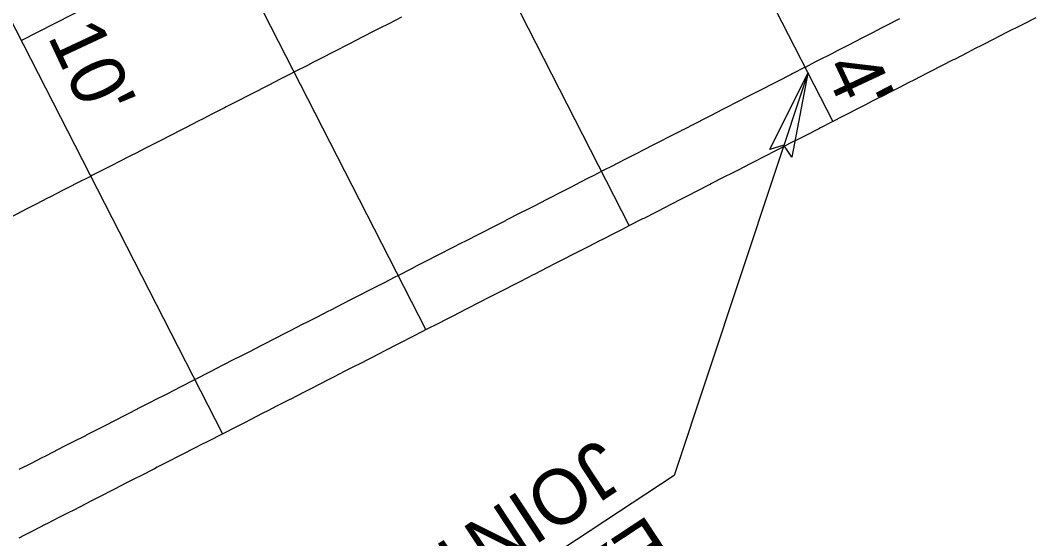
# Model space of a CAD drawing. Extents: x 2145147 to 2158018, y 137519 to 148068.
# Drawn here: x 2149836.3 to 2149903, y 143253.3 to 143287.3 of the extents above; entities that cross this region are included whole.
import ezdxf

# ---------------------------------------------------------------- set-up
doc = ezdxf.new("R2010")
doc.units = 0
for name, color, linetype in [('PR_Align_Service_C_Leader', 7, 'Continuous'), ('PR_Align_Service_C_Txt', 7, 'Continuous'), ('PR_Arrows', 7, 'Continuous'), ('PR_Dimensions', 7, 'Continuous'), ('PR_Joint_Contraction', 7, 'Continuous'), ('PR_Joint_Isolation', 7, 'Continuous'), ('PR_Joint_Long', 7, 'Continuous'), ('PR_Road_Concrete', 7, 'Continuous')]:
    doc.layers.add(name, color=color, linetype=linetype)

msp = doc.modelspace()

# ---------------------------------------------------------------- linework, layer by layer
at = {"layer": 'PR_Align_Service_C_Leader'}
msp.add_lwpolyline([(2149887.995, 143283.862), (2149879.208, 143257.447), (2149850.812, 143238.737)], dxfattribs=at)
at = {"layer": 'PR_Arrows'}
msp.add_lwpolyline([(2149887.995, 143283.862), (2149886.949, 143278.347), (2149886.421, 143279.131), (2149885.498, 143278.839)], close=True, dxfattribs=at)
at = {"layer": 'PR_Joint_Contraction'}
for p, q in [((2149859.056, 143307.493), (2149876.27, 143273.847)), ((2149847.09, 143297.948), (2149862.916, 143267.015)), ((2149835.031, 143288.585), (2149849.562, 143260.183))]:
    msp.add_line(p, q, dxfattribs=at)
at = {"layer": 'PR_Joint_Isolation'}
msp.add_line((2149876.415, 143306.496), (2149889.624, 143280.679), dxfattribs=at)
at = {"layer": 'PR_Joint_Long'}
msp.add_line((2149876.415, 143306.497), (2149836.353, 143286.001), dxfattribs=at)
for points in [[(2149861.301, 143287.53), (2149860.471, 143287.106), (2149859.85, 143286.788), (2149859.581, 143286.65), (2149858.691, 143286.195), (2149858.398, 143286.045), (2149857.801, 143285.739), (2149856.946, 143285.302), (2149856.91, 143285.284), (2149856.02, 143284.828), (2149855.495, 143284.559), (2149855.13, 143284.373), (2149854.24, 143283.917), (2149854.043, 143283.817), (2149853.349, 143283.462), (2149852.591, 143283.074), (2149852.459, 143283.006), (2149851.569, 143282.551), (2149851.139, 143282.331), (2149850.679, 143282.095), (2149849.788, 143281.64), (2149849.688, 143281.588), (2149848.898, 143281.185), (2149848.236, 143280.846), (2149848.008, 143280.729), (2149847.118, 143280.274), (2149846.784, 143280.103), (2149846.227, 143279.818), (2149845.337, 143279.363), (2149845.332, 143279.36), (2149844.447, 143278.907), (2149843.881, 143278.618), (2149843.557, 143278.452), (2149842.666, 143277.996), (2149842.429, 143277.875), (2149841.776, 143277.541), (2149840.977, 143277.132), (2149840.886, 143277.085), (2149839.996, 143276.63), (2149839.525, 143276.389), (2149839.105, 143276.174), (2149838.215, 143275.719), (2149838.074, 143275.647), (2149837.325, 143275.263), (2149836.622, 143274.904), (2149836.435, 143274.808), (2149835.544, 143274.353)], [(2149894.011, 143287.416), (2149893.121, 143286.96), (2149892.813, 143286.803), (2149892.23, 143286.505), (2149891.361, 143286.06), (2149891.34, 143286.049), (2149890.45, 143285.594), (2149889.909, 143285.317), (2149889.56, 143285.138), (2149888.669, 143284.683), (2149888.458, 143284.575), (2149887.807, 143284.242), (2149887.802, 143284.239), (2149887.779, 143284.228), (2149887.006, 143283.832), (2149886.889, 143283.772), (2149885.999, 143283.317), (2149885.554, 143283.089), (2149885.108, 143282.861), (2149884.218, 143282.406), (2149884.102, 143282.346), (2149883.328, 143281.95), (2149882.651, 143281.604), (2149882.438, 143281.495), (2149881.547, 143281.039), (2149881.199, 143280.861), (2149880.657, 143280.584), (2149879.767, 143280.128), (2149879.747, 143280.118), (2149879.683, 143280.086), (2149879.683, 143280.085), (2149878.877, 143279.673), (2149878.296, 143279.376), (2149877.986, 143279.217), (2149877.096, 143278.762), (2149876.844, 143278.633), (2149876.206, 143278.306), (2149875.392, 143277.89), (2149875.316, 143277.851), (2149874.425, 143277.396), (2149873.94, 143277.147), (2149873.535, 143276.94), (2149872.645, 143276.485), (2149872.489, 143276.405), (2149871.755, 143276.029), (2149871.037, 143275.662), (2149870.864, 143275.574), (2149869.974, 143275.118), (2149869.585, 143274.919), (2149869.084, 143274.663), (2149868.194, 143274.207), (2149868.133, 143274.176), (2149867.303, 143273.752), (2149866.682, 143273.434), (2149866.413, 143273.296), (2149865.523, 143272.841), (2149865.23, 143272.691), (2149864.633, 143272.385), (2149863.778, 143271.948), (2149863.742, 143271.93), (2149862.852, 143271.474), (2149862.327, 143271.206), (2149861.962, 143271.019), (2149861.072, 143270.564), (2149860.875, 143270.463), (2149860.181, 143270.108), (2149859.423, 143269.72), (2149859.291, 143269.653), (2149858.401, 143269.197), (2149857.971, 143268.977), (2149857.511, 143268.742), (2149856.62, 143268.286), (2149856.52, 143268.235), (2149855.73, 143267.831), (2149855.068, 143267.492), (2149854.84, 143267.375), (2149853.95, 143266.92), (2149853.616, 143266.749), (2149853.059, 143266.464), (2149852.169, 143266.009), (2149852.164, 143266.007), (2149851.279, 143265.553), (2149850.713, 143265.264), (2149850.389, 143265.098), (2149849.498, 143264.642), (2149849.261, 143264.521), (2149848.608, 143264.187), (2149847.809, 143263.778), (2149847.718, 143263.732), (2149846.828, 143263.276), (2149846.357, 143263.036), (2149845.937, 143262.821), (2149845.047, 143262.365), (2149844.906, 143262.293), (2149844.157, 143261.91), (2149843.454, 143261.55), (2149843.267, 143261.454), (2149842.376, 143260.999), (2149842.002, 143260.807), (2149841.486, 143260.543), (2149840.596, 143260.088), (2149840.551, 143260.065), (2149839.706, 143259.632), (2149839.099, 143259.322), (2149838.815, 143259.177), (2149837.925, 143258.721), (2149837.647, 143258.579), (2149837.035, 143258.266), (2149836.195, 143257.837)]]:
    msp.add_lwpolyline(points, dxfattribs=at)
at = {"layer": 'PR_Road_Concrete'}
msp.add_lwpolyline([(2149902.955, 143287.498), (2149902.065, 143287.043), (2149901.893, 143286.955), (2149901.174, 143286.588), (2149900.442, 143286.213), (2149900.284, 143286.132), (2149899.394, 143285.677), (2149898.99, 143285.47), (2149898.504, 143285.221), (2149897.613, 143284.766), (2149897.538, 143284.727), (2149896.723, 143284.31), (2149896.086, 143283.985), (2149895.833, 143283.855), (2149894.943, 143283.399), (2149894.635, 143283.242), (2149894.052, 143282.944), (2149893.183, 143282.499), (2149893.162, 143282.488), (2149892.272, 143282.033), (2149891.731, 143281.756), (2149891.382, 143281.577), (2149890.491, 143281.122), (2149890.28, 143281.014), (2149889.629, 143280.681), (2149889.624, 143280.678), (2149889.601, 143280.667), (2149888.828, 143280.271), (2149888.711, 143280.211), (2149887.821, 143279.756), (2149887.376, 143279.528), (2149886.93, 143279.3), (2149886.04, 143278.845), (2149885.924, 143278.785), (2149885.15, 143278.389), (2149884.473, 143278.043), (2149884.26, 143277.934), (2149883.369, 143277.478), (2149883.021, 143277.3), (2149882.479, 143277.023), (2149881.589, 143276.567), (2149881.569, 143276.557), (2149881.505, 143276.524), (2149881.504, 143276.524), (2149880.699, 143276.112), (2149880.117, 143275.815), (2149879.808, 143275.656), (2149878.918, 143275.201), (2149878.666, 143275.072), (2149878.028, 143274.745), (2149877.214, 143274.329), (2149877.137, 143274.29), (2149876.247, 143273.835), (2149875.762, 143273.586), (2149875.357, 143273.379), (2149874.467, 143272.924), (2149874.31, 143272.844), (2149873.576, 143272.468), (2149872.859, 143272.101), (2149872.686, 143272.013), (2149871.796, 143271.557), (2149871.407, 143271.358), (2149870.906, 143271.102), (2149870.015, 143270.646), (2149869.955, 143270.615), (2149869.125, 143270.191), (2149868.504, 143269.873), (2149868.235, 143269.735), (2149867.345, 143269.28), (2149867.052, 143269.13), (2149866.454, 143268.824), (2149865.6, 143268.387), (2149865.564, 143268.369), (2149864.674, 143267.913), (2149864.148, 143267.645), (2149863.784, 143267.458), (2149862.893, 143267.003), (2149862.697, 143266.902), (2149862.003, 143266.547), (2149861.245, 143266.159), (2149861.113, 143266.092), (2149860.223, 143265.636), (2149859.793, 143265.416), (2149859.332, 143265.181), (2149858.442, 143264.725), (2149858.341, 143264.674), (2149857.552, 143264.27), (2149856.89, 143263.931), (2149856.662, 143263.814), (2149855.771, 143263.359), (2149855.438, 143263.188), (2149854.881, 143262.903), (2149853.991, 143262.448), (2149853.986, 143262.445), (2149853.101, 143261.992), (2149852.535, 143261.703), (2149852.21, 143261.537), (2149851.32, 143261.081), (2149851.083, 143260.96), (2149850.43, 143260.626), (2149849.631, 143260.217), (2149849.54, 143260.171), (2149848.649, 143259.715), (2149848.179, 143259.475), (2149847.759, 143259.26), (2149846.869, 143258.804), (2149846.728, 143258.732), (2149845.979, 143258.349), (2149845.276, 143257.989), (2149845.088, 143257.893), (2149844.198, 143257.438), (2149843.824, 143257.246), (2149843.308, 143256.982), (2149842.418, 143256.527), (2149842.372, 143256.504), (2149841.527, 143256.071), (2149840.921, 143255.761), (2149840.637, 143255.616), (2149839.747, 143255.16), (2149839.469, 143255.018), (2149838.857, 143254.705), (2149838.017, 143254.276), (2149837.966, 143254.249), (2149837.076, 143253.794), (2149836.566, 143253.533), (2149836.186, 143253.339)], dxfattribs=at)

# ---------------------------------------------------------------- texts
at = {"layer": 'PR_Align_Service_C_Txt'}
for s, p in [('JOINT', (2149874.277, 143259.938)), ('EXPANSION', (2149877.578, 143254.928))]:
    msp.add_text(s, height=3.6, rotation=213.38021, dxfattribs=at).set_placement(p)
at = {"layer": 'PR_Dimensions'}
for s, p in [("10'", (2149838.04, 143286.288)), ("4'", (2149888.966, 143284.216))]:
    msp.add_text(s, height=3.6, rotation=295.10211, dxfattribs=at).set_placement(p)

doc.saveas('drawing.dxf')
